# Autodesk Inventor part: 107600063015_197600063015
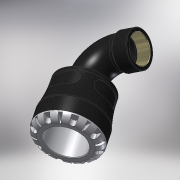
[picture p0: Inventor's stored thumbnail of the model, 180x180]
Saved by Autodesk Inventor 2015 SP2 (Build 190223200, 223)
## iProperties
Created: 2016-12
Part Number: 107600063015_197600063015
Material: PVC-Piping
Description: PLASSON 90° ELBOW WITH FEMALE INTEGRAL BRASS 63X1.1/2" SERIES 1
Document SubType Name: Modeling
Designer: KIM
Mass: 664.223 g
Surface Area: 733.008 cm^2
Volume: 474.445 cm^3
Density: 1.4 g/cm^3
Appearance: Black Cast
Author: KIM
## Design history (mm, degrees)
derived "1076.ipt"
feature "Solid1::1076.ipt"
tag "TaggingFeature1"
body "Solid1"
other parameters: "d1" = 37.8, "d2" = 63, "d3" = 78.75, "d4" = 103, "d8" = 90.64, "d13" = 9.7, "d14" = 9.7, "d15" = 0, "d17" = 360 deg, "d19" = 8 deg, "d20" = 1.26, "d21" = 1.26, "d22" = 8 deg, "d24" = 0, "d26" = 360 deg, "d33" = 10.3, "d51" = 1.03, "d54" = 22.05, "d55" = 13.86, "d57" = 19.012, "d58" = 0, "d74" = 0, "d82" = 1.26, "d115" = 360 deg, "d207" = 90 deg, "d228" = 18.7425, "d248" = 5.4, "d270" = 143, "d279" = 72, "d281" = 6.72675, "d294" = 44.845, "d295" = 21, "d296" = 23.1, "d297" = 40.3605, "d299" = 52.46865, "d300" = 40.3605, "d301" = 0, "d302" = 0, "d306" = 2.91492, "d309" = 90.9, "d310" = 19.08568, "d312" = 15 deg, "d313" = 0.824, "d314" = 10.26, "d315" = 0.515, "d_" = 63, "E_" = 103, "A_" = 143, "A_1" = 72, "l_2" = 21, "Rp_" = 44.845, "d9" = 12.125, "d11" = 103, "d12" = 78.75, "d298" = 58.2985
